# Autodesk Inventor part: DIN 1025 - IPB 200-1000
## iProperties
Created: 2007-02
Part Number: DIN 1025 - IPB 200-1000
Material: Stahl, weich, unlegiert
Description: Warmgewalzte I-Träger IPB
Document SubType Name: Modeling
Standard: DIN 1025
Designer: thomas
Standards Organization: DIN
Language: de-DE
Size Designation: IPB 200-1000
Categories: <MemberInstance><Categories><Category DisplayName="Profilstähle" InternalName="089c4875-fa83-4c05-b084-43b9cc11f5ed" Mnemonic="GRDR"><CategoryParameter DisplayN
Stock Number: IPB 200
Density: 7.86 g/cm^3
G_L: 1000,000 mm
IsCustomPart: 1
Author: thomas
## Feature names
1. Extrusion1
